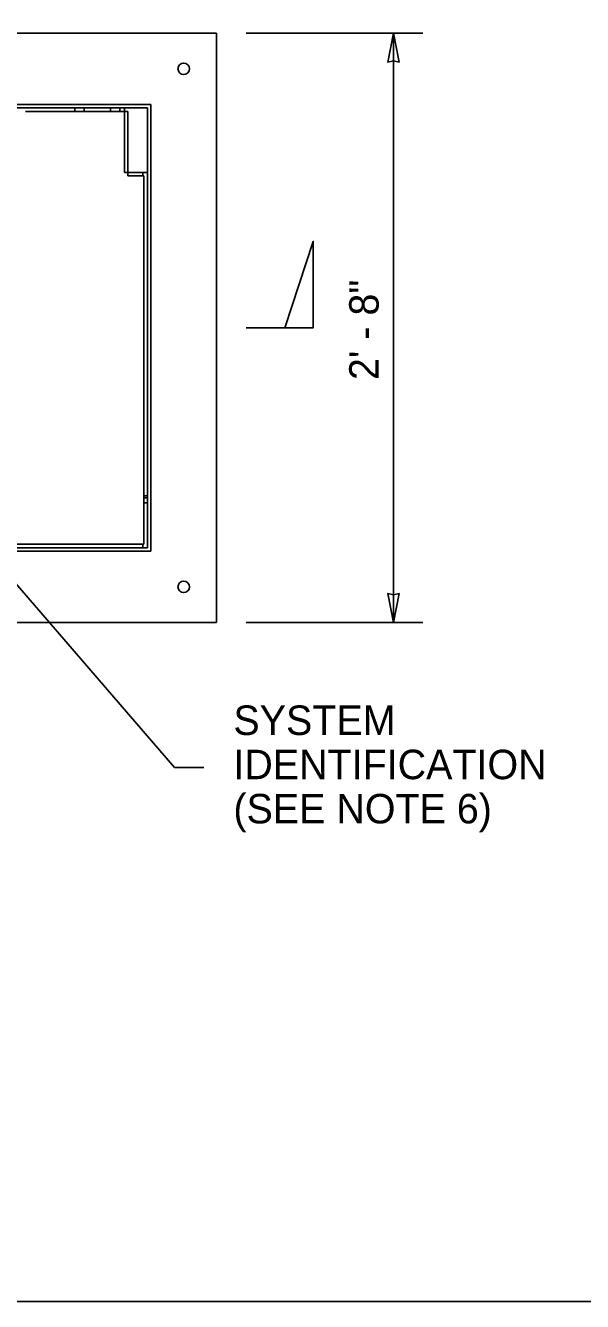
# Model space of a CAD drawing. Extents: x 99862 to 103151, y 100000 to 105076.
# Drawn here: x 100411 to 100713, y 100000 to 100692 of the extents above; entities that cross this region are included whole.
import ezdxf

# ---------------------------------------------------------------- set-up
doc = ezdxf.new("R2010")
doc.units = 0
for name, color, linetype in [('Level 1', 7, 'Continuous'), ('Level 15', 7, 'Continuous'), ('Level 20', 7, 'Continuous'), ('Level 3', 7, 'Continuous'), ('Level 4', 7, 'Continuous'), ('Level 5', 7, 'Continuous')]:
    doc.layers.add(name, color=color, linetype=linetype)

msp = doc.modelspace()

# ---------------------------------------------------------------- linework, layer by layer
at = {"layer": 'Level 1'}
msp.add_lwpolyline([(99862, 99999.5), (103151, 99999.5), (103151, 102075.5), (99862, 102075.5)], close=True, dxfattribs=at)
at = {"layer": 'Level 15'}
for p, q in [((100530.69, 100687.98), (100626.69, 100687.98)), ((100610.69, 100367.98), (100610.69, 100687.98)), ((100491.85, 100289.35), (100294.69, 100517.99)), ((100530.69, 100367.98), (100626.69, 100367.98)), ((100507.85, 100289.35), (100491.85, 100289.35))]:
    msp.add_line(p, q, dxfattribs=at)
for points in [[(100610.69, 100687.98), (100607.61, 100672.26), (100610.69, 100672.99), (100613.78, 100672.26)], [(100610.69, 100367.98), (100607.61, 100383.71), (100610.69, 100382.98), (100613.78, 100383.71)]]:
    msp.add_lwpolyline(points, close=True, dxfattribs=at)
at = {"layer": 'Level 20'}
msp.add_line((100530.69, 100527.98), (100567.22, 100527.98), dxfattribs=at)
msp.add_lwpolyline([(100551.69, 100527.99), (100567.22, 100574.87), (100567.22, 100527.99)], close=True, dxfattribs=at)
at = {"layer": 'Level 3'}
for p, q in [((100074.69, 100687.98), (100514.69, 100687.98)), ((100514.69, 100687.98), (100514.69, 100367.98)), ((100110.32, 100649.23), (100479.07, 100649.23)), ((100479.07, 100649.23), (100479.07, 100406.73)), ((100474.69, 100612.36), (100474.69, 100610.48)), ((100474.69, 100410.48), (100474.69, 100408.61)), ((100479.07, 100406.73), (100110.32, 100406.73)), ((100514.69, 100367.98), (100074.69, 100367.98))]:
    msp.add_line(p, q, dxfattribs=at)
for centre in [(100496.88, 100668.61), (100496.88, 100387.36)]:
    msp.add_circle(centre, 3.12, dxfattribs=at)
at = {"layer": 'Level 4'}
for p, q in [((100124.69, 100647.36), (100464.69, 100647.36)), ((100477.19, 100612.36), (100477.19, 100408.61)), ((100477.19, 100408.61), (100112.19, 100408.61))]:
    msp.add_line(p, q, dxfattribs=at)
for points, degree in [([(100475.51, 100436.73), (100475.44, 100436.73), (100475.38, 100436.73), (100475.32, 100436.73)], 2), ([(100475.32, 100435.8), (100475.38, 100435.8), (100475.58, 100435.8), (100475.9, 100435.8), (100476.3, 100435.8), (100476.7, 100435.8), (100477, 100435.8), (100477.16, 100435.8), (100477.19, 100435.8)], 3), ([(100475.51, 100432.99), (100475.44, 100432.99), (100475.38, 100432.99), (100475.32, 100432.99)], 2), ([(100475.9, 100436.73), (100475.84, 100436.73), (100475.7, 100436.73), (100475.57, 100436.73), (100475.51, 100436.73)], 3), ([(100475.9, 100432.99), (100475.84, 100432.99), (100475.7, 100432.99), (100475.57, 100432.99), (100475.51, 100432.99)], 3), ([(100476.3, 100436.73), (100476.24, 100436.73), (100476.1, 100436.73), (100475.97, 100436.73), (100475.9, 100436.73)], 3), ([(100476.3, 100432.99), (100476.24, 100432.99), (100476.1, 100432.99), (100475.97, 100432.99), (100475.9, 100432.99)], 3), ([(100476.7, 100436.73), (100476.64, 100436.73), (100476.5, 100436.73), (100476.37, 100436.73), (100476.3, 100436.73)], 3), ([(100476.7, 100432.99), (100476.64, 100432.99), (100476.5, 100432.99), (100476.37, 100432.99), (100476.3, 100432.99)], 3), ([(100477.1, 100436.73), (100477.04, 100436.73), (100476.9, 100436.73), (100476.77, 100436.73), (100476.7, 100436.73)], 3), ([(100477.1, 100432.99), (100477.04, 100432.99), (100476.9, 100432.99), (100476.77, 100432.99), (100476.7, 100432.99)], 3), ([(100477.19, 100436.73), (100477.16, 100436.73), (100477.13, 100436.73), (100477.1, 100436.73)], 2), ([(100477.19, 100432.99), (100477.16, 100432.99), (100477.13, 100432.99), (100477.1, 100432.99)], 2)]:
    msp.add_open_spline(points, degree=degree, dxfattribs=at)
at = {"layer": 'Level 5'}
for p, q in [((100437.82, 100647.36), (100437.82, 100645.48)), ((100442.82, 100647.36), (100442.82, 100645.48)), ((100457.19, 100647.36), (100457.19, 100645.48)), ((100462.19, 100647.36), (100462.19, 100645.48)), ((100464.69, 100647.36), (100477.19, 100647.36)), ((100464.69, 100612.36), (100464.69, 100647.36)), ((100477.19, 100647.36), (100477.19, 100612.36)), ((100411.03, 100645.48), (100413.53, 100645.48)), ((100418.29, 100645.48), (100413.53, 100645.48)), ((100420.79, 100645.48), (100418.29, 100645.48)), ((100431.03, 100645.48), (100420.79, 100645.48)), ((100433.53, 100645.48), (100431.03, 100645.48)), ((100438.29, 100645.48), (100433.53, 100645.48)), ((100440.79, 100645.48), (100438.29, 100645.48)), ((100451.03, 100645.48), (100440.79, 100645.48)), ((100453.53, 100645.48), (100451.03, 100645.48)), ((100458.29, 100645.48), (100453.53, 100645.48)), ((100460.79, 100645.48), (100458.29, 100645.48)), ((100466.57, 100645.48), (100460.79, 100645.48)), ((100466.57, 100610.48), (100466.57, 100645.48)), ((100477.19, 100612.36), (100464.69, 100612.36)), ((100470.41, 100610.48), (100466.57, 100610.48)), ((100470.41, 100610.48), (100472.91, 100610.48)), ((100475.32, 100610.48), (100472.91, 100610.48)), ((100475.32, 100602.45), (100475.32, 100610.48)), ((100475.32, 100602.45), (100475.32, 100600.33)), ((100475.32, 100590.91), (100475.32, 100600.33)), ((100475.32, 100588.78), (100475.32, 100590.91)), ((100475.32, 100578.68), (100475.32, 100588.78)), ((100475.32, 100578.68), (100475.28, 100578.66)), ((100475.32, 100578.68), (100475.32, 100577.2)), ((100475.32, 100567.13), (100475.32, 100577.2)), ((100475.32, 100567.13), (100475.32, 100565.65)), ((100475.32, 100555.59), (100475.32, 100565.65)), ((100475.32, 100554.1), (100475.32, 100555.59)), ((100475.32, 100544.04), (100475.32, 100554.1)), ((100475.32, 100544.04), (100475.28, 100544.02)), ((100475.28, 100542.57), (100475.32, 100542.55)), ((100475.32, 100542.55), (100475.32, 100544.04)), ((100475.32, 100532.49), (100475.32, 100542.55)), ((100475.32, 100532.49), (100475.28, 100532.47)), ((100475.28, 100531.03), (100475.32, 100531.01)), ((100475.32, 100531.01), (100475.32, 100532.49)), ((100475.32, 100520.94), (100475.32, 100531.01)), ((100475.32, 100520.94), (100475.28, 100520.92)), ((100475.28, 100519.48), (100475.32, 100519.46)), ((100475.32, 100520.94), (100475.32, 100519.46)), ((100475.32, 100509.4), (100475.32, 100519.46)), ((100475.32, 100509.4), (100475.28, 100509.38)), ((100475.28, 100507.93), (100475.32, 100507.91)), ((100475.32, 100509.4), (100475.32, 100507.91)), ((100475.32, 100497.85), (100475.32, 100507.91)), ((100475.32, 100496.37), (100475.32, 100497.85)), ((100475.32, 100486.3), (100475.32, 100496.37)), ((100475.32, 100486.3), (100475.28, 100486.28)), ((100475.28, 100484.84), (100475.32, 100484.82)), ((100475.32, 100484.82), (100475.32, 100486.3)), ((100475.32, 100474.76), (100475.32, 100484.82)), ((100475.32, 100474.76), (100475.28, 100474.74)), ((100475.28, 100473.29), (100475.32, 100473.27)), ((100475.32, 100473.27), (100475.32, 100474.76)), ((100475.32, 100463.93), (100475.32, 100473.27)), ((100475.32, 100463.93), (100475.32, 100461.73)), ((100475.32, 100452.38), (100475.32, 100461.73)), ((100475.32, 100452.38), (100475.32, 100450.18)), ((100475.32, 100440.84), (100475.32, 100450.18)), ((100475.32, 100440.84), (100475.32, 100438.63)), ((100475.32, 100429.29), (100475.32, 100438.63)), ((100475.32, 100427.08), (100475.32, 100429.29)), ((100475.32, 100417.74), (100475.32, 100427.08)), ((100475.32, 100417.74), (100475.32, 100415.54)), ((100382.75, 100410.48), (100446.57, 100410.48)), ((100446.57, 100410.48), (100462.75, 100410.48)), ((100466.57, 100410.48), (100462.75, 100410.48)), ((100466.57, 100410.48), (100475.32, 100410.48)), ((100475.32, 100410.48), (100475.32, 100415.54))]:
    msp.add_line(p, q, dxfattribs=at)

# ---------------------------------------------------------------- texts
at = {"layer": 'Level 20'}
msp.add_text('2\' - 8"', height=16, rotation=90, dxfattribs=at).set_placement((100602.69, 100499.65))
for s, p in [('SYSTEM', (100523.85, 100307)), ('IDENTIFICATION', (100523.85, 100283)), ('(SEE NOTE 6)', (100523.85, 100259))]:
    msp.add_text(s, height=16, dxfattribs=at).set_placement(p)

doc.saveas('drawing.dxf')
